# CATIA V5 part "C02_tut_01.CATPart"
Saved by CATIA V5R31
Part number: C02_Tut1
Bounding box of the stored display mesh (mm): x 0 to 0, y 0 to 120, z 0 to 59.981
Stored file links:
  D:\PROJECTS\Project 2021\US EDITION\CATIA V5 6R 2021\Resources\Tutorial Files\c02_catia_v5_6r2021_tut\C02_tut_01.CATPart
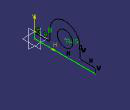
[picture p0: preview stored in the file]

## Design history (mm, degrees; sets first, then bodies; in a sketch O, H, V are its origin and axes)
Body1 (main body)
  Sketch1 on yz-plane, origin (0, 0, 0), H (0, 1, 0), V (0, 0, 1)
    line L1 (0, 0) -> (120, 0)
    line L2 (120, 0) -> (120, 10)
    line L3 (120, 10) -> (90, 10)
    line L4 (90, 10) -> (90, 30)
    arc A1 centre (60, 30) radius 30 from (90, 30) to (30, 30) ccw
    line L5 (30, 30) -> (30, 10)
    line L6 (30, 10) -> (0, 10)
    point P8 (0, 10)
    line L7 (0, 10) -> (0, 0)
    circle A2 centre (60, 30) radius 15
    radius A2 = 15
    horizontal: L1 H, L3 H, L6 H
    vertical: L2 V, L4 V, L7 V
    tangency: A1 L4, L5 A1
    coincidence: P8 V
